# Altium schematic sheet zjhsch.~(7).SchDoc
size A4
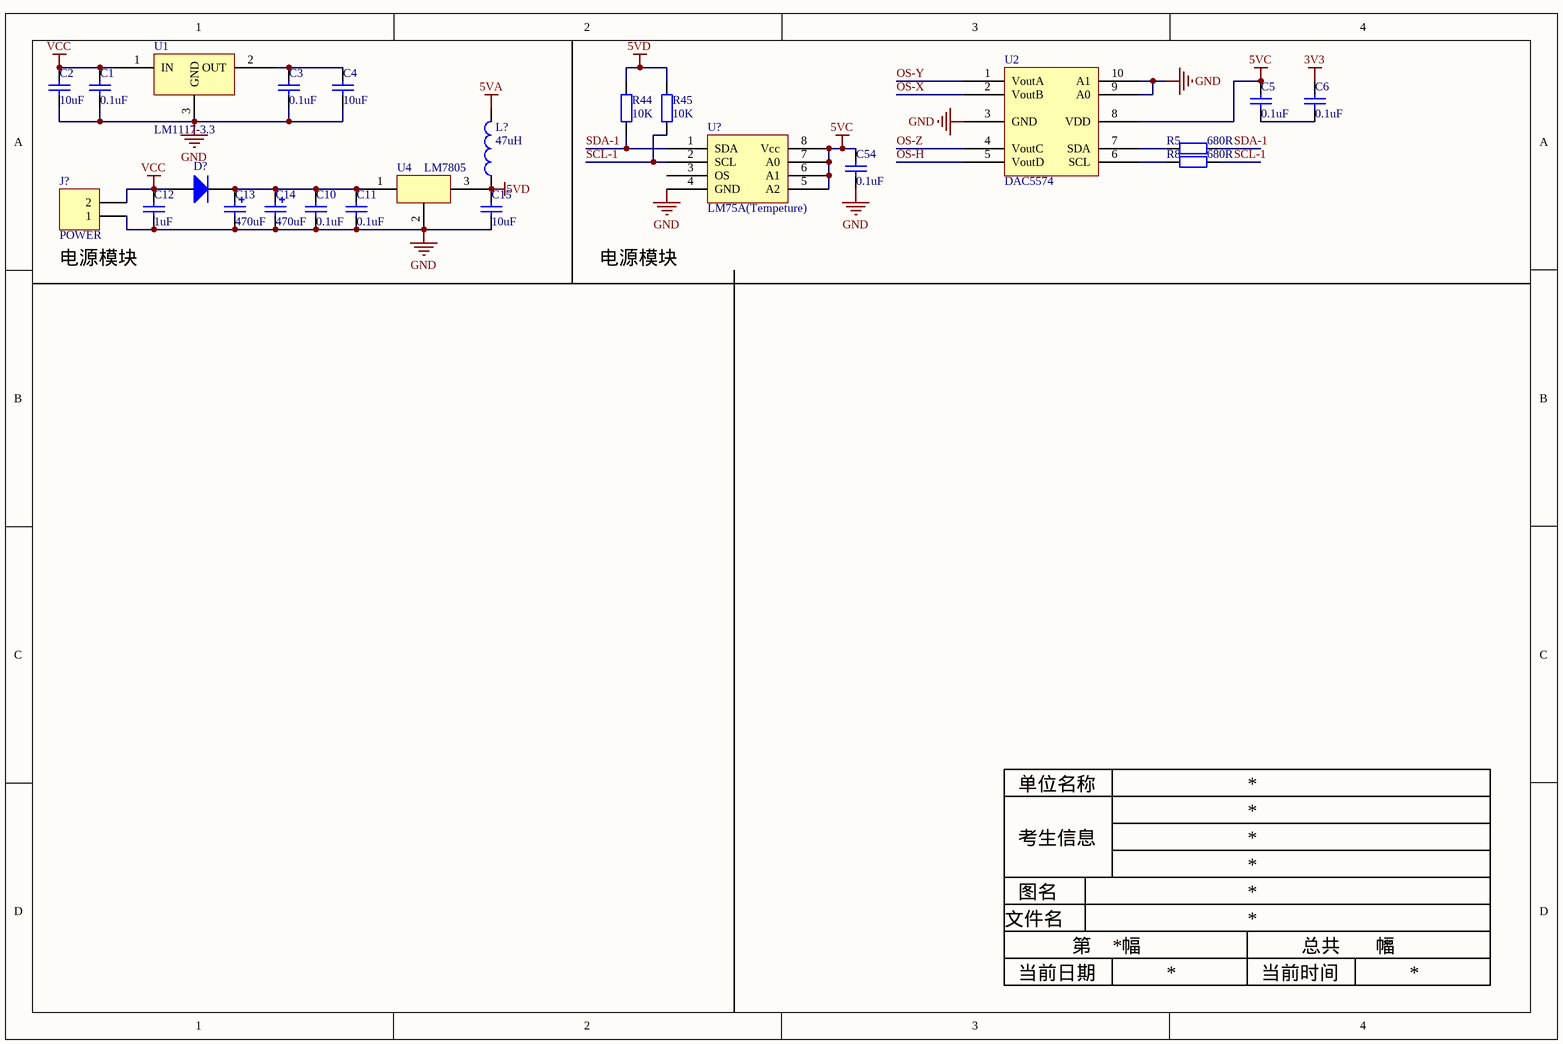
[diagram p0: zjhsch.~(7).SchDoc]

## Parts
C1  value 0.1uF  [RAD-0.3]  (hidden comment: Cap)
C2  value 10uF  [RAD-0.3]  (hidden comment: Cap)
C3  value 0.1uF  [RAD-0.3]  (hidden comment: Cap)
C4  value 10uF  [RAD-0.3]  (hidden comment: Cap)
C5  value 0.1uF  [RAD-0.3]  (hidden comment: Cap)
C6  value 0.1uF  [RAD-0.3]  (hidden comment: Cap)
C10  value 0.1uF  [RAD-0.3]  (hidden comment: Cap)
C11  value 0.1uF  [RAD-0.3]  (hidden comment: Cap)
C12  value 1uF  [RAD-0.3]  (hidden comment: Cap)
C13  value 470uF  [POLAR0.8]  (hidden comment: Cap Pol2)
C14  value 470uF  [POLAR0.8]  (hidden comment: Cap Pol2)
C15  value 10uF  [RAD-0.3]  (hidden comment: Cap)
C54  value 0.1uF  [RAD-0.3]  (hidden comment: Cap)
D?  Diode  [SMC]  (value not drawn)
J?  POWER  [HDR1X2]
L?  47uH  [DIODE_SMC]
R5  680R  [R0603]
R8  680R  [R0603]
R44  10K  [1608[0603]]
R45  10K  [1608[0603]]
U1  LM1117-3.3  [LM1117-3.3]
U2  DAC5574
U4  LM7805  [TO-220AB]
U?  LM75A(Tempeture)  [LM75A]

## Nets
3V3: C6.2
5VA: L?.2
5VC: C5.2 C54.2 U2.8(VDD) U?.5(A2) U?.6(A1) U?.7(A0) U?.8(Vcc)
5VD: C15.2 L?.1 R44.2 R45.2 U4.3
GND: C1.1 C2.1 C3.1 C4.1 C10.1 C11.1 C12.1 C13.2 C14.2 C15.1 C54.1 J?.1 U1.3(GND) U2.3(GND) U2.9(A0) U2.10(A1) U4.2 U?.4(GND)
VCC: C1.2 C2.2 C12.2 D?.1(A) J?.2 U1.1(IN)
OS-H: U2.5(VoutD)
OS-X: U2.2(VoutB)
OS-Y: U2.1(VoutA)
OS-Z: U2.4(VoutC)
SCL-1: R8.2 R45.1 U?.2(SCL)
SDA-1: R5.2 R44.1 U?.1(SDA)
NetC3_2: C3.2 C4.2 U1.2(OUT)
NetC5_1: C5.1 C6.1
NetC10_2: C10.2 C11.2 C13.1 C14.1 D?.2(K) U4.1
NetR5_1: R5.1 U2.7(SDA)
NetR8_1: R8.1 U2.6(SCL)

Not connected (* = marked no-connect by the designer): U? 3(OS)

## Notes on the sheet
- 单位名称
- 考生信息
- 文件名
- 图名
- 当前日期
- 第      幅
- 当前时间
- 总共       幅
- Labels drawn without touching a wire or pin: 电源模块

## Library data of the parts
C1-C6 C10-C12 C15 C54 = Cap: Capacitor
C13 C14 = Cap Pol2: Polarized Capacitor (Axial)
D? = Diode: Default Diode
J? = Header 2: Header, 2-Pin
L? = Inductor47uH
R5 R8 = R0603
R44 R45 = R0805
U4 = 7805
